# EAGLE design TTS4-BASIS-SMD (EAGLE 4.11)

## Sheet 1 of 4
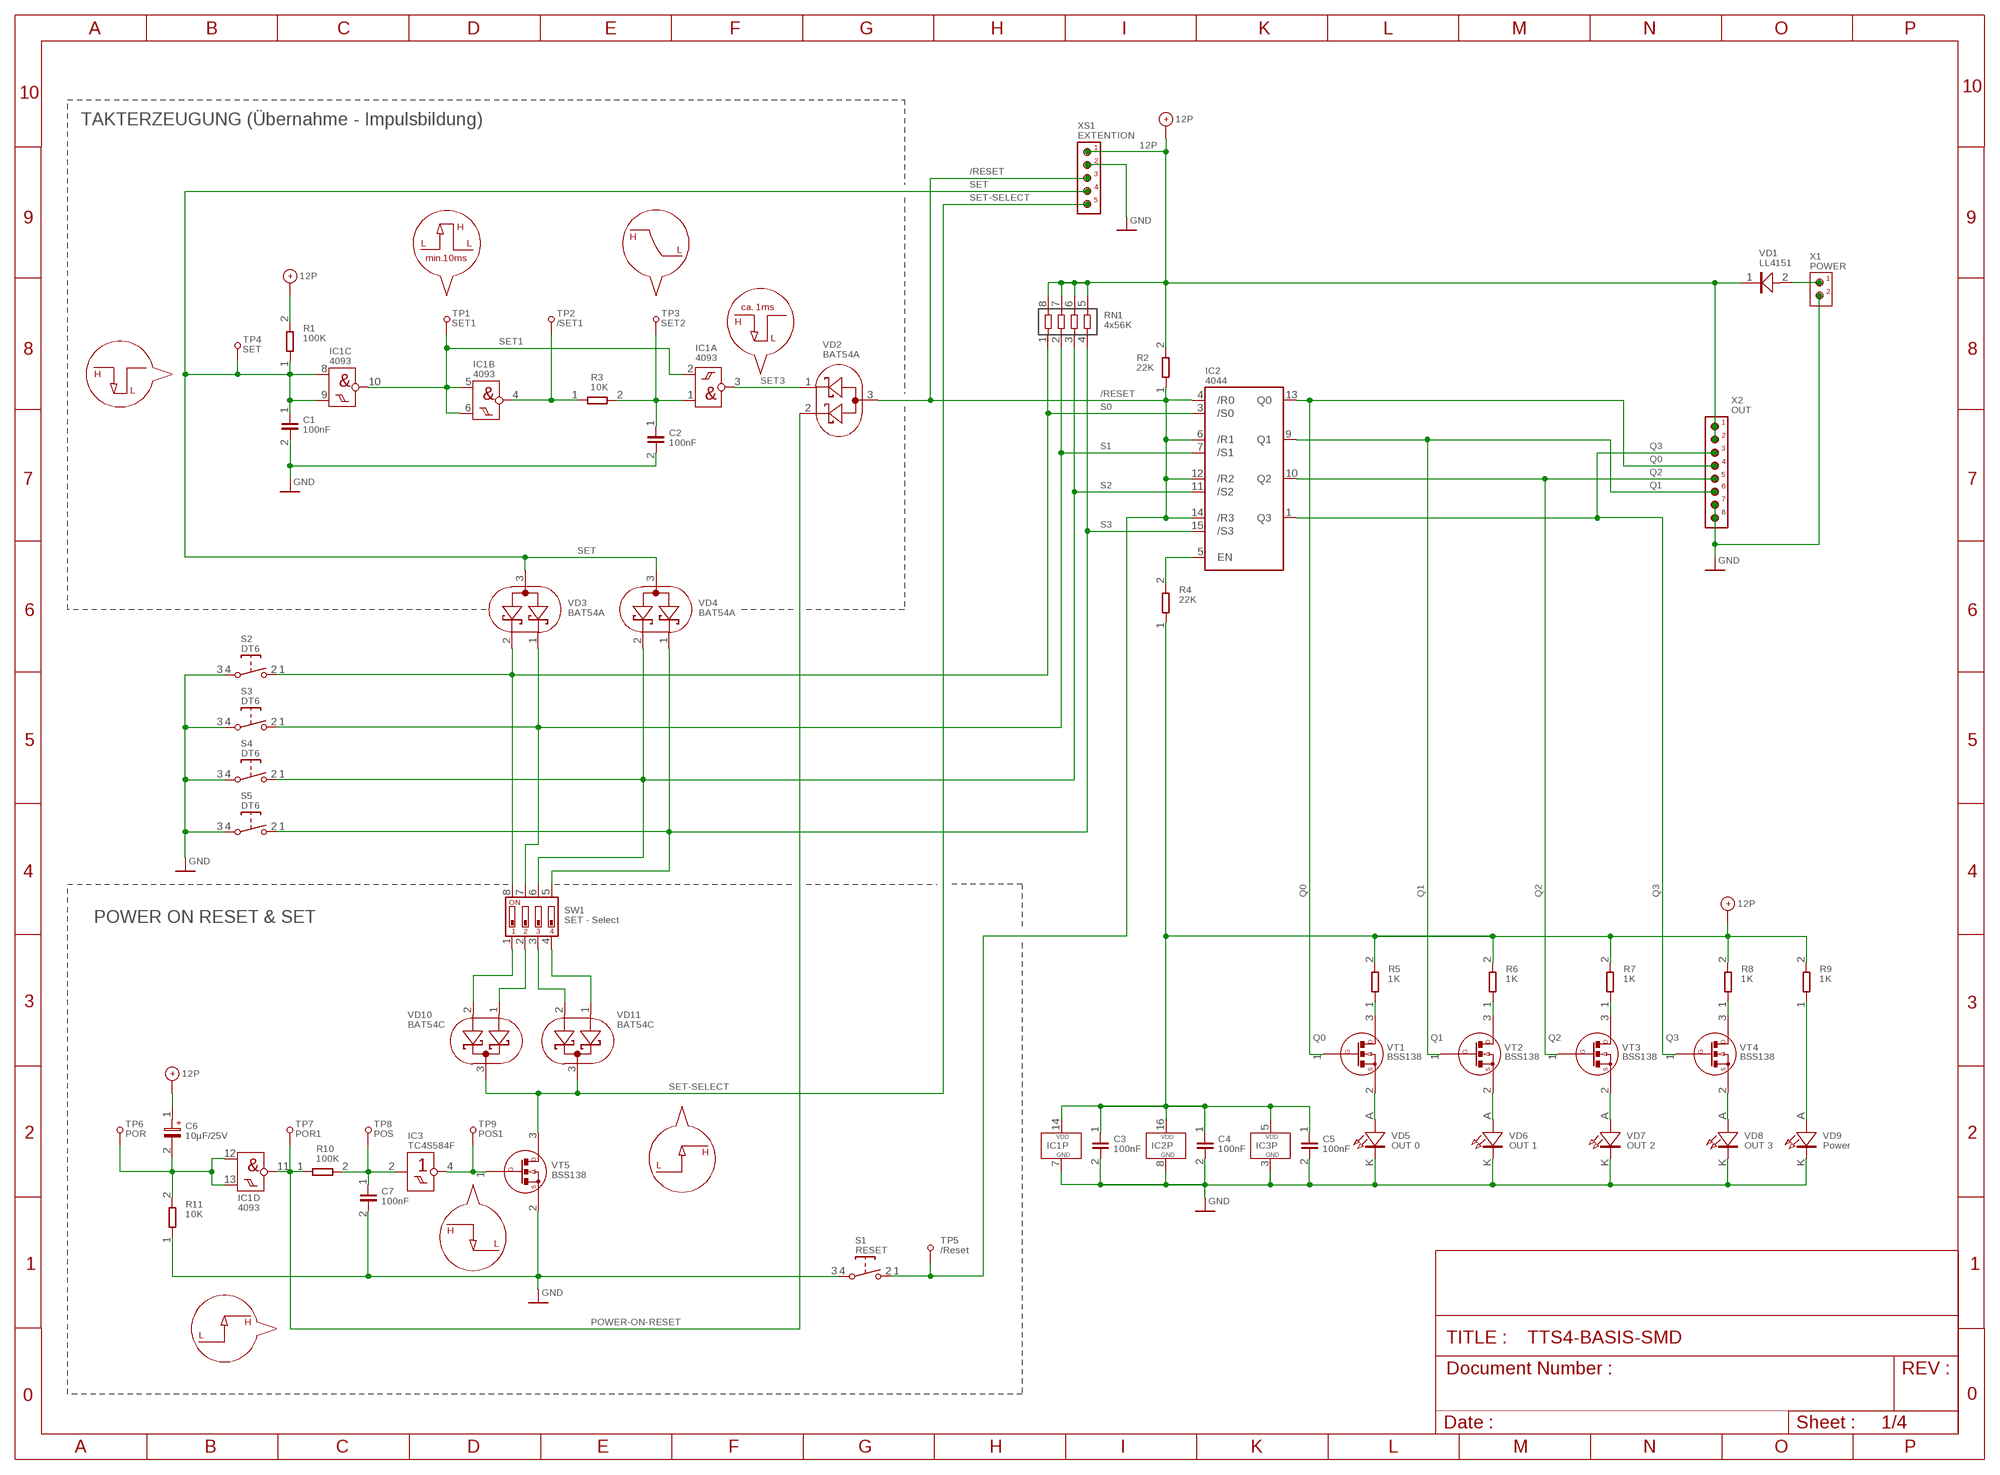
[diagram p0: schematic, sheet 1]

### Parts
C1  100nF  C-SMD_0603S  [0603S]
C2  100nF  C-SMD_0603S  [0603S]
C3  100nF  C-SMD_0603S  [0603S]
C4  100nF  C-SMD_0603S  [0603S]
C5  100nF  C-SMD_0603S  [0603S]
C6  10µF/25V  SMD-ELKO_6032  [6032]
C7  100nF  C-SMD_0603S  [0603S]
IC1  4093  4093_SO  [SO14]
IC2  4044  4044_SO  [SO16]
IC3  TC4S584F  TC4S584F_S  [SOT23/5_S]
R1  100K  R-SMD_0603S  [0603S]
R2  22K  R-SMD_0603S  [0603S]
R3  10K  R-SMD_0603S  [0603S]
R4  22K  R-SMD_0603S  [0603S]
R5  1K  R-SMD_1206S  [1206S]
R6  1K  R-SMD_1206S  [1206S]
R7  1K  R-SMD_1206S  [1206S]
R8  1K  R-SMD_1206S  [1206S]
R9  1K  R-SMD_1206S  [1206S]
R10  100K  R-SMD_0603S  [0603S]
R11  10K  R-SMD_0603S  [0603S]
RN1  4x56K  RNCAT16L  [RNCAT16]
S1  RESET  DT6-H  [DT6-HOLE]
S2  DT6  DT6-H  [DT6-HOLE]
S3  DT6  DT6-H  [DT6-HOLE]
S4  DT6  DT6-H  [DT6-HOLE]
S5  DT6  DT6-H  [DT6-HOLE]
SW1  SET - Select  SW_DIP-4SMS  [SMS4]
TP1  SET1  TP1.5  [TP1.5MM]
TP2  /SET1  TP1.5  [TP1.5MM]
TP3  SET2  TP1.5  [TP1.5MM]
TP4  SET  TP1.5  [TP1.5MM]
TP5  /Reset  TP1.5  [TP1.5MM]
TP6  POR  TP1.5  [TP1.5MM]
TP7  POR1  TP1.5  [TP1.5MM]
TP8  POS  TP1.5  [TP1.5MM]
TP9  POS1  TP1.5  [TP1.5MM]
VD1  LL4151  LL4151_N  [MLL34]
VD2  BAT54A  BAT54AL  [SOT23L]
VD3  BAT54A  BAT54AL  [SOT23L]
VD4  BAT54A  BAT54AL  [SOT23L]
VD5  OUT 0  LED3MM  [LED-3MM]
VD6  OUT 1  LED3MM  [LED-3MM]
VD7  OUT 2  LED3MM  [LED-3MM]
VD8  OUT 3  LED3MM  [LED-3MM]
VD9  Power  LED3MM  [LED-3MM]
VD10  BAT54C  BAT54C_L  [SOT23L]
VD11  BAT54C  BAT54C_L  [SOT23L]
VT1  BSS138  BSS138_L  [SOT23L]
VT2  BSS138  BSS138_L  [SOT23L]
VT3  BSS138  BSS138_L  [SOT23L]
VT4  BSS138  BSS138_L  [SOT23L]
VT5  BSS138  BSS138_L  [SOT23L]
X1  POWER  PAD2_PF  [1X2]
X2  OUT  PAD8_PF  [1X8]
XS1  EXTENTION  PF1X5  [1X5]

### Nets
12P: C3.1 C4.1 C5.1 C6.1(+) IC1.14(P:VDD) IC2.16(VDD) IC3.5(VDD) R1.2 R2.2 R4.1 R5.2 R6.2 R7.2 R8.2 R9.2 RN1.5 RN1.6 RN1.7 RN1.8 VD1.1(K) X2.1 X2.2 XS1.1
/RESET: IC2.4(/R0) IC2.6(/R1) IC2.12(/R2) IC2.14(/R3) R2.1 S1.1(S) S1.2(S) TP5.1 VD2.3(A) XS1.3
/SET1: IC1.4(B:O) R3.1 TP2.1
GND: C1.2 C2.2 C3.2 C4.2 C5.2 C7.2 IC1.7(P:GND) IC2.8(GND) IC3.3(GND) R11.1 S1.3(P) S1.4(P) S2.3(P) S2.4(P) S3.3(P) S3.4(P) S4.3(P) S4.4(P) S5.3(P) S5.4(P) VD5.K VD6.K VD7.K VD8.K VD9.K VT5.2(S) X1.2 X2.7 X2.8 XS1.2
N$1: VD1.2(A) X1.1
N$5: VD5.A VT1.2(S)
N$6: VD6.A VT2.2(S)
N$7: VD7.A VT3.2(S)
N$8: VD8.A VT4.2(S)
N$9: IC2.5(EN) R4.2
N$11: R5.1 VT1.3(D)
N$12: R6.1 VT2.3(D)
N$13: R7.1 VT3.3(D)
N$14: R8.1 VT4.3(D)
N$19: R9.1 VD9.A
POR: C6.2(-) IC1.12(D:I0) IC1.13(D:I1) R11.2 TP6.1
POS: C7.1 IC3.2(I) R10.2 TP8.1
POS1: IC3.4(O) TP9.1 VT5.1(G)
POWER-ON-RESET: IC1.11(D:O) R10.1 TP7.1 VD2.2(K2)
Q0: IC2.13(Q0) VT1.1(G) X2.4
Q1: IC2.9(Q1) VT2.1(G) X2.6
Q2: IC2.10(Q2) VT3.1(G) X2.5
Q3: IC2.1(Q3) VT4.1(G) X2.3
S0: IC2.3(/S0) RN1.1 S2.1(S) S2.2(S) SW1.8 VD3.2(K2)
S1: IC2.7(/S1) RN1.2 S3.1(S) S3.2(S) SW1.7 VD3.1(K1)
S2: IC2.11(/S2) RN1.3 S4.1(S) S4.2(S) SW1.6 VD4.2(K2)
S3: IC2.15(/S3) RN1.4 S5.1(S) S5.2(S) SW1.5 VD4.1(K1)
SET: C1.1 IC1.8(C:I0) IC1.9(C:I1) R1.1 TP4.1 VD3.3(A) VD4.3(A) XS1.4
SET1: IC1.2(A:I1) IC1.5(B:I0) IC1.6(B:I1) IC1.10(C:O) TP1.1
SET2: C2.1 IC1.1(A:I0) R3.2 TP3.1
SET3: IC1.3(A:O) VD2.1(K1)
SET-SELECT: VD10.3(K) VD11.3(K) VT5.3(D) XS1.5
SL1: SW1.1 VD10.2(A2)
SL2: SW1.2 VD10.1(A1)
SL3: SW1.3 VD11.2(A2)
SL4: SW1.4 VD11.1(A1)

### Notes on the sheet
- TAKTERZEUGUNG (Übernahme - Impulsbildung)
- H
- H
- L | L
- L
- min.10ms
- ca. 1ms
- H
- L
- H
- L
- POWER ON RESET & SET
- H
- L
- H
- L
- H
- L

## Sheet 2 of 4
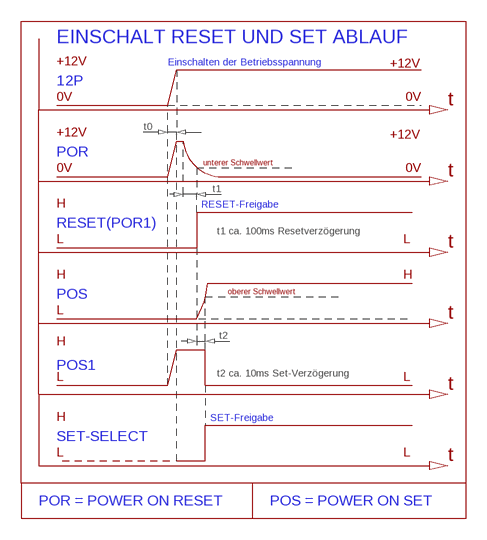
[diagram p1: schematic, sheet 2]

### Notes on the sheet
- EINSCHALT RESET UND SET ABLAUF
- +12V | Einschalten der Betriebsspannung | +12V
- 12P
- 0V | 0V
- t
- t0
- +12V | +12V
- POR
- unterer Schwellwert
- 0V | 0V
- t
- t1
- H | RESET-Freigabe
- RESET(POR1)
- t1 ca. 100ms Resetverzögerung
- L | L
- t
- H | H
- oberer Schwellwert
- POS
- L
- t
- t2
- H
- POS1
- t2 ca. 10ms Set-Verzögerung
- L | L
- t
- H | SET-Freigabe
- SET-SELECT
- L | L
- t
- POR = POWER ON RESET | POS = POWER ON SET

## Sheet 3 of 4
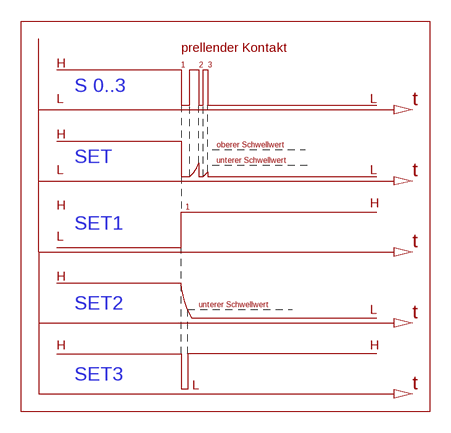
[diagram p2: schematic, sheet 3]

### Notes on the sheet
- prellender Kontakt
- H | 1 | 2 | 3
- S 0..3
- L | L | t
- H
- oberer Schwellwert
- SET | unterer Schwellwert
- L | L | t
- H | 1 | H
- SET1
- L
- t
- H
- SET2 | unterer Schwellwert
- L
- t
- H | H
- SET3
- L | t

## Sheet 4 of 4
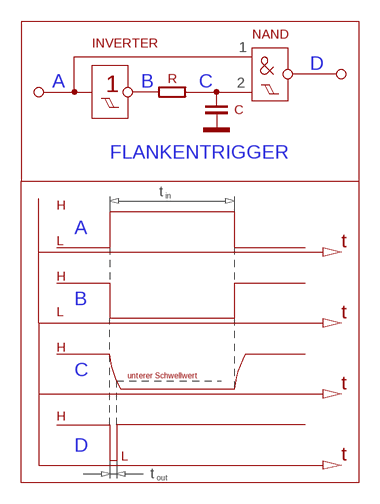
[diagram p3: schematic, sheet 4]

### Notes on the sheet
- NAND
- INVERTER
- 1
- D
- R
- A | 1 | B | C | 2
- C
- FLANKENTRIGGER
- t | in
- H
- A
- L | t
- H
- B
- L | t
- H
- C | unterer Schwellwert
- t
- H
- D
- L | t
- t | out

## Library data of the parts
C1-C5 C7 = RLC - SMD:C-SMD_: SMD - Kondensator
C6 = RLC - SMD:SMD-ELKO_: SMD - Elko
IC1 = 40XXSMD:4093_: vier NAND Gatter mit je zwei Schmitt - Trigger - Eingängen
IC2 = 40XXSMD:4044_: vier RS - Flip - Flop mit Tristate - Ausgängen
IC3 = TOSHIBA:TC4S584F_: 1 INVERTER mit Schmitt - Trigger Eingang , Code : CA
R1-R11 = RLC - SMD:R-SMD_: SMD - Widerstände
RN1 = RLC - SMD:RNCAT16: SMD - Widerstandsnetz , 4 unabhängige Einzelwiderstände
S1-S5 = SWITCH:DT: ITT SWITCH
SW1 = DIL - SW:SW_DIP-4
TP1-TP9 = CON1:TP: Testpunkt mit 2 mm Durchmesser
VD1 = SMD:LL4151_
VD2-VD4 = DC:BAT54A
VD5-VD9 = OPTO:LED
VD10 VD11 = DC:BAT54C_: Doppelschottkydiode mit gemeinsamer Katode
VT1-VT5 = DC:BSS138_: N - Kanal MOSFET
X1 = PAD:PAD2_: 2 Lötpads
X2 = PAD:PAD8_: 8 Lötpads
XS1 = PF:PF1X5

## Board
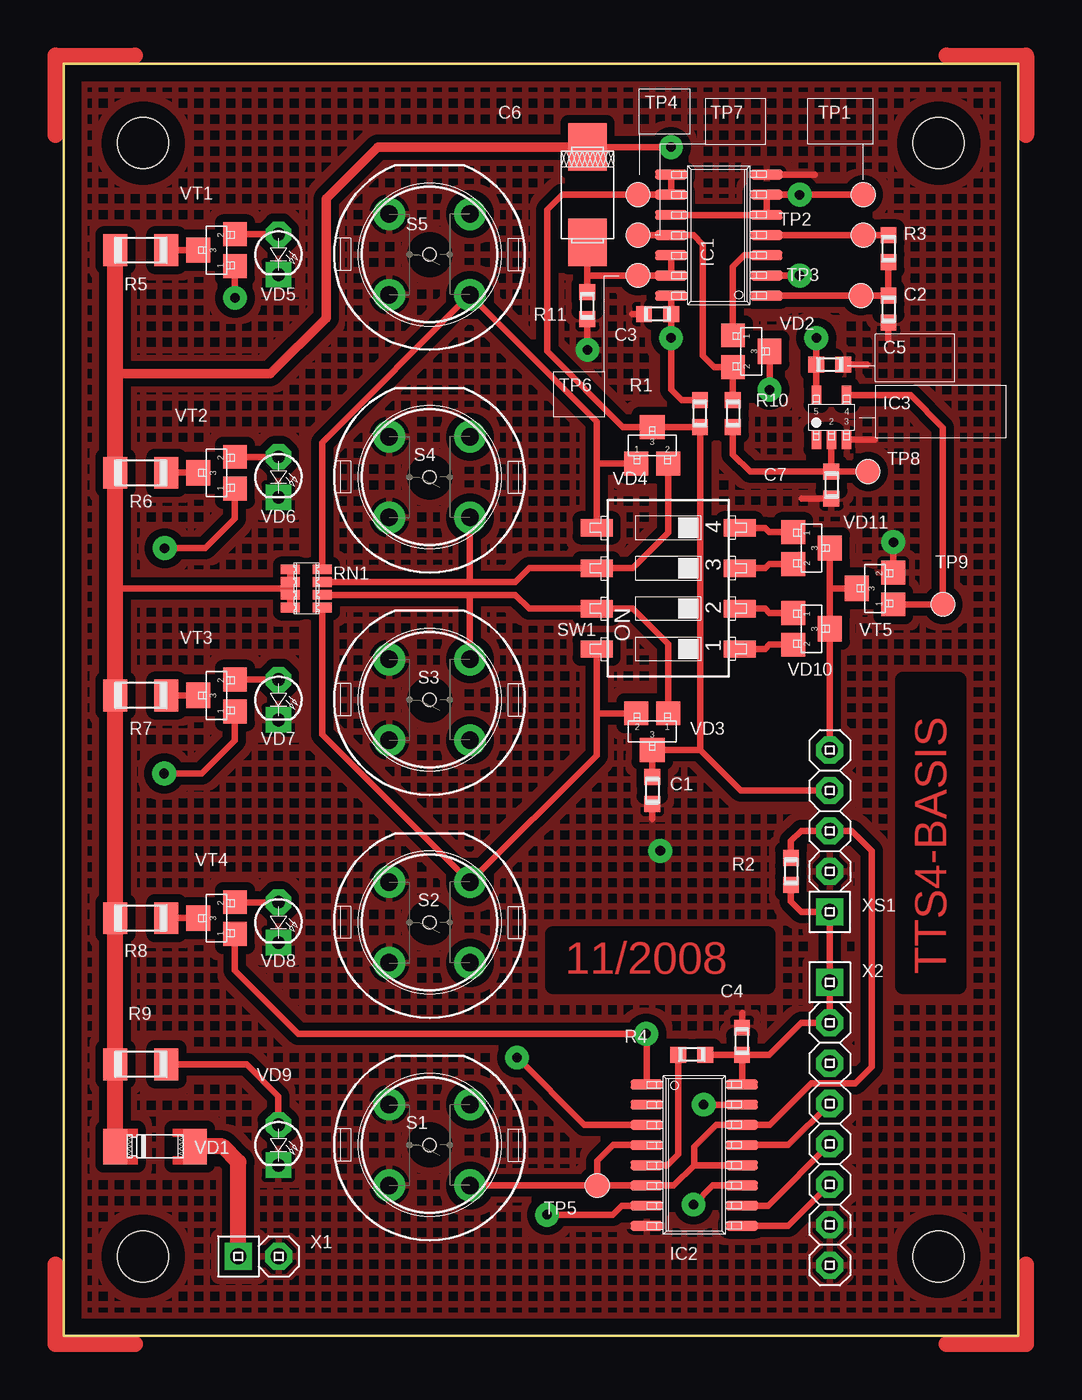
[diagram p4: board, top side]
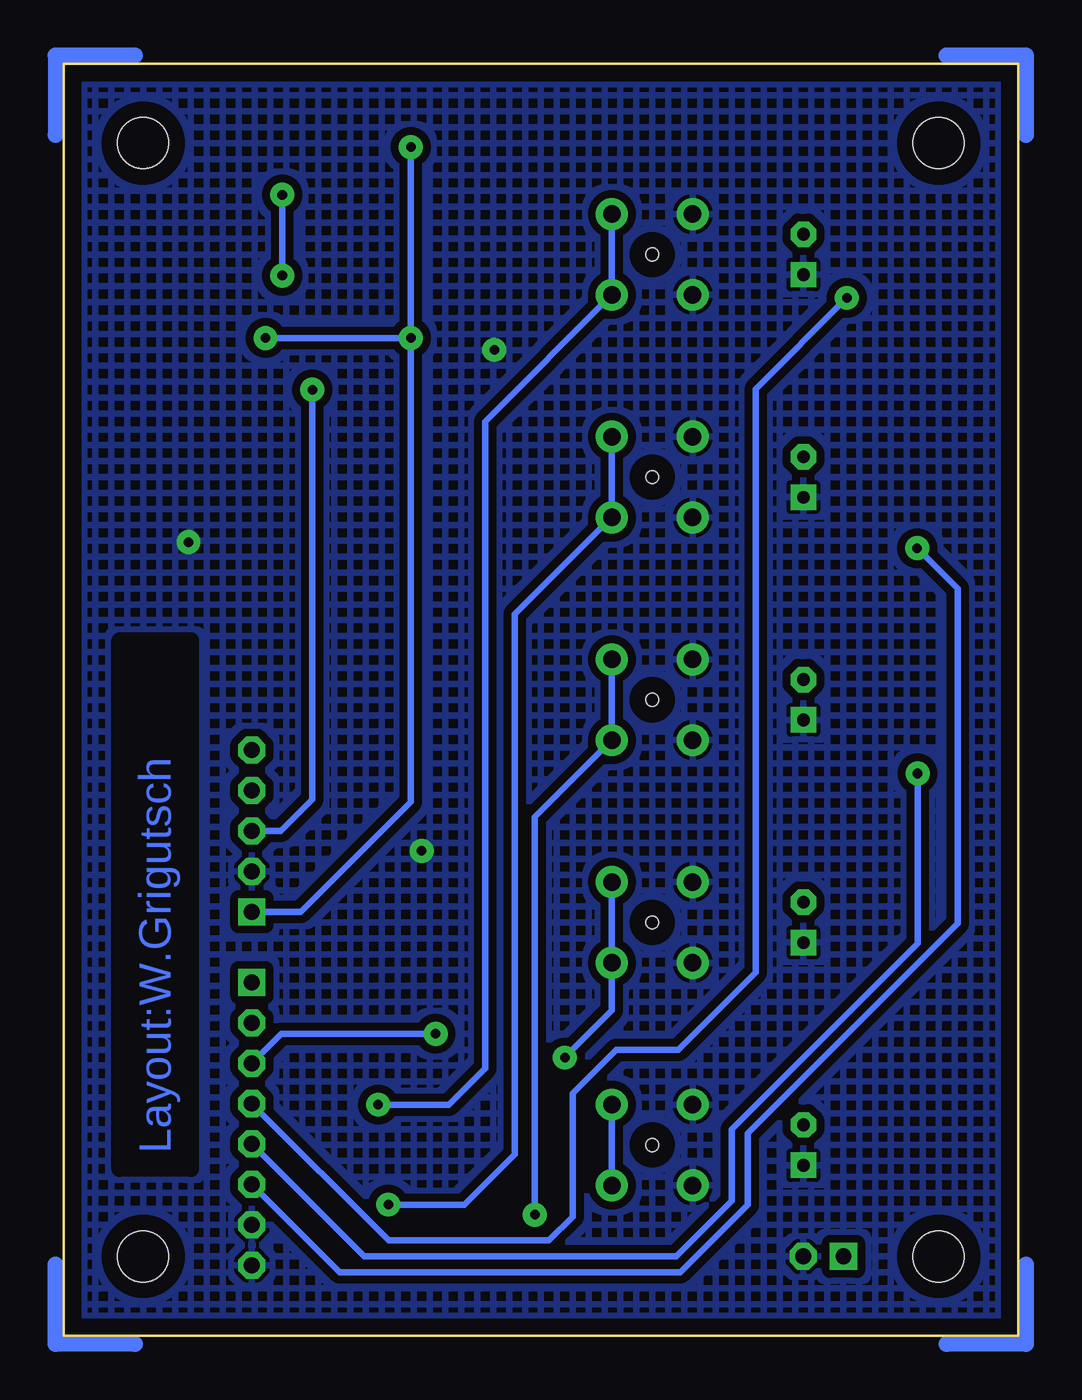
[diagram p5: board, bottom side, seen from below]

Size 60 x 80 mm. Coordinates in mm from the lower left corner, seen from the top.
Outline: 0,0 60,0 60,80 0,80 0,0
Copper layers (1*16): Top 0.035mm / dielectric 1.5mm / Bottom 0.035mm
Design rules "default": minimum track width 10mil, minimum drill 20mil, track to track 8mil, track to pad 8mil, pad to pad 8mil, via to via 8mil, smd to smd 8mil, copper to edge 40mil, drill to drill 8mil, minimum pad ring 10mil, minimum via ring 8mil, stop-mask expansion 4mil, vias tented up to drill 0mil, thermal gap 10mil
Holes 3.2 mm at 5,5 55,5 5,75 55,75
tRestrict: area 52.8,22 to 56.2,41.2; area 30.8,22 to 44.2,25.2
bRestrict: area 52,10.5 to 56.5,43.8

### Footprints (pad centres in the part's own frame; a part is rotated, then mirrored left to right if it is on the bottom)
0603S = smd 1 x 1: 1 -0.85,0; 2 0.85,0
6032 = smd 3 x 2.4: 1 -3,0; 2 3,0
SO14 = smd 0.61 x 2: 1 -3.81,-3; 2 -2.54,-3; 3 -1.27,-3; 4 0,-3; 5 1.27,-3; 6 2.54,-3; 7 3.81,-3; 8 3.81,3; 9 2.54,3; 10 1.27,3; 11 0,3; 12 -1.27,3; 13 -2.54,3; 14 -3.81,3
SO16 = smd 0.61 x 2: 1 -4.445,-3; 2 -3.175,-3; 3 -1.905,-3; 4 -0.635,-3; 5 0.635,-3; 6 1.905,-3; 7 3.175,-3; 8 4.445,-3; 9 4.445,3; 10 3.175,3; 11 1.905,3; 12 0.635,3; 13 -0.635,3; 14 -1.905,3; 15 -3.175,3; 16 -4.445,3
SOT23/5_S = smd 0.6 x 1.2: 1 -0.95,-1.4; 2 0,-1.4; 3 0.95,-1.4; 4 0.95,1.4; 5 -0.95,1.4
1206S = smd 1.5 x 2: 1 -1.6,0; 2 1.6,0
RNCAT16 = smd 0.6 x 1.2: 1 -1.2,-1; 2 -0.4,-1; 3 0.4,-1; 4 1.2,-1; 5 1.2,1; 6 0.4,1; 7 -0.4,1; 8 -1.2,1
DT6-HOLE = drill 1.1 pad 2 round: 1 -2.54,2.54; 2 2.54,2.54; 3 2.54,-2.54; 4 -2.54,-2.54 | hole 0.8: 0,0
SMS4 = smd 1.092 x 2.007: 1 -3.81,-4.496; 2 -1.27,-4.496; 3 1.27,-4.496; 4 3.81,-4.496; 5 3.81,4.496; 6 1.27,4.496; 7 -1.27,4.496; 8 -3.81,4.496
TP1.5MM = smd 1.5 x 1.5: 1 0,0
MLL34 = smd 1.5 x 2.25: 1 -2.5,0; 2 2.5,0
SOT23L = smd 1.5 x 1.5: 1 -1,-1.15; 2 1,-1.15 | smd 1.6 x 1.5: 3 0,1.15
LED-3MM = drill 0.8 pad 1.6 octagon: A 1.27,0 | drill 0.8 pad 1.6 square: K -1.27,0
1X2 = drill 1 pad 1.7 square: 1 -1.27,0 | drill 1 pad 1.7 octagon: 2 1.27,0
1X8 = drill 1 pad 1.7 square: 1 -8.89,0 | drill 1 pad 1.7 octagon: 2 -6.35,0; 3 -3.81,0; 4 -1.27,0; 5 1.27,0; 6 3.81,0; 7 6.35,0; 8 8.89,0
1X5 = drill 1 pad 1.7 square: 1 -5.08,0 | drill 1 pad 1.7 octagon: 2 -2.54,0; 3 0,0; 4 2.54,0; 5 5.08,0

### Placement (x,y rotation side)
C1  37,34.29 270 top
C2  51.85,64.56 270 top
C3  37.33,64.25 180 top
C4  42.64,18.53 90 top
C5  48.16,61.09 0 top
C6  32.92,71.75 270 top
C7  48.26,53.5 270 top
IC1  41.18,69.22 90 top
IC2  39.64,11.37 270 top
IC3  48.26,57.75 0 top
R1  40,58 90 top
R2  45.72,29.21 270 top
R3  51.85,68.36 270 top
R4  39.49,17.68 180 top
R5  4.86,68.27 180 top
R6  4.86,54.27 180 top
R7  4.86,40.27 180 top
R8  4.86,26.27 180 top
R9  4.86,17.08 180 top
R10  42.07,58 270 top
R11  32.92,64.77 90 top
RN1  15.26,47 90 top
S1  23,12 270 top
S2  23,26 270 top
S3  23,40 270 top
S4  23,54 270 top
S5  23,68 270 top
SW1  38,47 90 top
TP1  50.26,71.75 270 top
TP2  50.26,69.22 0 top
TP3  50.12,65.41 180 top
TP4  36.1,71.75 90 top
TP5  33.54,9.46 270 top
TP6  36.1,66.67 180 top
TP7  36.1,69.22 90 top
TP8  50.56,54.35 180 top
TP9  55.27,46 270 top
VD1  5.75,11.9 0 top
VD2  43.22,61.91 270 top
VD3  37,38 180 top
VD4  37,56 0 top
VD5  13.5,68 90 top
VD6  13.5,54 90 top
VD7  13.5,40 90 top
VD8  13.5,26 90 top
VD9  13.5,12 90 top
VD10  47.02,44.46 270 top
VD11  47.02,49.54 270 top
VT1  9.62,68.27 90 top
VT2  9.62,54.27 90 top
VT3  9.62,40.27 90 top
VT4  9.62,26.27 90 top
VT5  51,47 90 top
X1  12.25,5 0 top
X2  48.16,13.34 270 top
XS1  48.16,31.75 90 top

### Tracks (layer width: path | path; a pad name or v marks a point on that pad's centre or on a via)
12P  (via drill 0.6 pad 1.5)
  Top 0.4: RN1.5 RN1.6 14.26,47 | 14.26,47 RN1.7 RN1.8 | C4.1 IC2.16 | C4.1 R4.1 | 3.25,47 14.26,47 | IC1.14 C3.1 v38.18,62.75 38.18,59.52 38.84,58.85 R1.2 | C6.1 v38.18,74.75 | R2.2 45.72,27.3 46.35,26.67 XS1.1 X2.1 X2.2 46.35,19.68 44.35,17.68 C4.1 | IC3.5 C5.1 v47.31,62.75
  Top 0.6: C6.1 19.75,74.75 16.5,71.5 16.5,64 13,60.5 3.25,60.5
  Top 1: R5.2 3.25,60.5 R6.2 3.25,47 R7.2 R8.2 R9.2 VD1.1
  Bottom 0.4: v38.18,74.75 v38.18,62.75 | v38.18,62.75 38.18,33.58 45.09,26.67 XS1.1 | v38.18,62.75 v47.31,62.75
/RESET  (via drill 0.6 pad 1.5)
  Top 0.4: S1.2 TP5.1 | TP5.1 IC2.6 38.37,9.46 39.63,10.73 | 39.63,10.73 IC2.12 | IC2.4 34.54,12 33.54,11 TP5.1 | 39.63,10.73 39.63,11.88 41.02,13.27 IC2.14 44.38,13.27 46.99,15.88 49.75,15.88 50.8,16.92 50.8,30.48 49.53,31.75 XS1.3 46.35,31.75 45.72,31.11 R2.1 | v44.37,59.5 VD2.3
  Bottom 0.4: S1.2 S1.1 | XS1.3 46.35,31.75 44.37,33.73 v44.37,59.5
/SET1
  Top 0.4: IC1.4 TP2.1 R3.1
GND  (via drill 0.6 pad 1.5)
  Top 0.4: IC1.7 47.21,73.03 | 51.85,62.65 C2.2 | C4.2 42.64,20.32 | 37,32.5 C1.2 | IC3.3 50.97,56.35 | 46.39,52.65 C7.2 | C3.2 35.75,64.25 | v32.92,62 R11.1 | VT5.2 v52.15,49.91 | C5.2 50.5,61.09
  other vias: 37.5,30.5
  pour Bottom (isolate 0.5, hatched): 1,1 1,79 59,79 59,1
  pour Top (isolate 0.5, hatched): 1,79 1,1 59,1 59,79
N$1
  Top 1: X1.1 10.98,10.93 10,11.9 VD1.2
N$2
  Top 1: 4.5,-0.5 -0.5,-0.5 -0.5,4.5
N$3
  Top 1: 55.5,-0.5 60.5,-0.5 60.5,4.5
N$4
  Top 1: 4.5,80.5 -0.5,80.5 -0.5,75.5
N$5
  Top 0.4: VT1.2 VD5.A
N$6
  Top 0.4: VT2.2 VD6.A
N$7
  Top 0.4: VT3.2 VD7.A
N$8
  Top 0.4: VT4.2 VD8.A
N$9
  Top 0.4: IC2.5 37.94,10.73 38.64,11.43 R4.2
N$10
  Top 1: 60.5,75.5 60.5,80.5 55.5,80.5
N$11
  Top 0.4: R5.1 VT1.3
N$12
  Top 0.4: R6.1 VT2.3
N$13
  Top 0.4: R7.1 VT3.3
N$14
  Top 0.4: R8.1 VT4.3
N$15
  Bottom 1: 4.5,-0.5 -0.5,-0.5 -0.5,4.5
N$16
  Bottom 1: 55.5,-0.5 60.5,-0.5 60.5,4.5
N$17
  Bottom 1: 4.5,80.5 -0.5,80.5 -0.5,75.5
N$18
  Bottom 1: 60.5,75.5 60.5,80.5 55.5,80.5
N$19
  Top 0.4: R9.1 11.49,17.08 13.5,15.07 VD9.A
POR
  Top 0.4: IC1.12 IC1.13 TP6.1 32.92,66.67 | R11.2 32.92,66.67 | 32.92,66.67 C6.2
POS
  Top 0.4: C7.1 IC3.2 | C7.1 TP8.1 | R10.2 42.07,55.43 43.15,54.35 C7.1
POS1
  Top 0.4: VT5.1 TP9.1 55.27,57.12 53.24,59.15 IC3.4
POWER-ON-RESET
  Top 0.4: TP7.1 IC1.11 39.59,69.22 40.18,68.63 40.18,61.64 40.91,60.91 VD2.2 R10.1
Q0  (via drill 0.6 pad 1.5)
  Top 0.4: IC2.13 45.56,12 X2.4 | v10.77,65.27 VT1.1
  Bottom 0.4: X2.4 39.56,6 29.5,6 28,7.5 28,15.25 25.25,18 21.37,18 16.51,22.86 16.51,59.53 v10.77,65.27
Q1  (via drill 0.6 pad 1.5)
  Top 0.4: IC2.9 45.56,6.92 X2.6 | VT2.1 10.77,51.41 8.89,49.53 v6.35,49.53
  Bottom 0.4: X2.6 42.64,4 21.25,4 17,8.25 17,12.75 3.81,25.94 3.81,46.99 v6.35,49.53
Q2  (via drill 0.6 pad 1.5)
  Top 0.4: IC2.10 44.29,8.19 X2.5 | v6.32,35.37 8.7,35.37 10.77,37.44 VT3.1
  Bottom 0.4: X2.5 41.1,5 21.5,5 18,8.5 18,13 6.32,24.68 v6.32,35.37
Q3  (via drill 0.6 pad 1.5)
  Top 0.4: IC2.1 36.64,19 v36.62,19 14.75,19 10.77,22.98 VT4.1
  Bottom 0.4: X2.3 46.31,19 v36.62,19
S0  (via drill 0.6 pad 1.5)
  Top 0.4: 33.5,39.15 33.5,36.5 S2.1 16.25,37.83 RN1.1 | 33.5,39.15 SW1.8 | 33.5,39.15 VD3.2 | IC2.3 32.73,13.27 v28.5,17.5
  Bottom 0.4: S2.1 S2.2 25.54,20.46 v28.5,17.5
S1  (via drill 0.6 pad 1.5)
  Top 0.4: 25.54,46.6 RN1.2 | 25.54,46.6 28.4,46.6 29.27,45.73 SW1.7 35.77,45.73 38,43.5 VD3.1 | S3.1 25.54,46.6 | IC2.7 35.08,8.19 34.51,7.62 v30.39,7.62
  Bottom 0.4: S3.1 S3.2 30.39,32.62 v30.39,7.62
S2  (via drill 0.6 pad 1.5)
  Top 0.4: 25.54,47.4 RN1.3 | 25.54,47.4 28.4,47.4 29.27,48.27 SW1.6 35.77,48.27 38,50.5 VD4.2 | S4.2 25.54,47.4 | IC2.11 40.8,9.46 v39.59,8.26
  Bottom 0.4: 25.54,51.5 S4.2 | 25.54,51.5 S4.1 | v39.59,8.26 34.83,8.26 31.66,11.43 31.66,45.38 25.54,51.5
S3  (via drill 0.6 pad 1.5)
  Top 0.4: 33.5,54.85 33.5,57.5 S5.2 16.25,56.17 RN1.4 | 33.5,54.85 SW1.5 | 33.5,54.85 VD4.1 | v40.23,14.54 IC2.15
  Bottom 0.4: S5.1 S5.2 33.5,57.5 33.5,16.83 35.79,14.54 v40.23,14.54
SET
  Top 0.4: IC1.8 IC1.9 TP4.1 31.34,71.75 30.39,70.8 30.39,61.91 35.15,57.15 VD4.3 R1.1 40,36.85 | 40,36.85 VD3.3 C1.1 | 40,36.85 42.56,34.29 XS1.4
SET1  (via drill 0.6 pad 1.5)
  Top 0.4: IC1.10 IC1.5 IC1.6 v46.26,71.75 TP1.1 | v46.26,66.67 IC1.2
  Bottom 0.4: v46.26,71.75 v46.26,66.67
SET2
  Top 0.4: IC1.1 TP3.1 C2.1 R3.2
SET3
  Top 0.4: IC1.3 42.77,67.94 42.07,67.25 VD2.1
SET-SELECT
  Top 0.4: 48.16,47 VD10.3 48.16,42.5 XS1.5 | 48.16,47 VD11.3 | 48.16,47 VT5.3
SL1
  Top 0.4: SW1.1 44.09,43.19 44.37,43.46 VD10.2
SL2
  Top 0.4: SW1.2 44.09,45.73 44.37,45.46 VD10.1
SL3
  Top 0.4: SW1.3 44.09,48.27 44.37,48.54 VD11.2
SL4
  Top 0.4: SW1.4 44.09,50.81 44.37,50.54 VD11.1

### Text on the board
Top: 11/2008 | TTS4-BASIS
Bottom: Layout:W.Grigutsch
